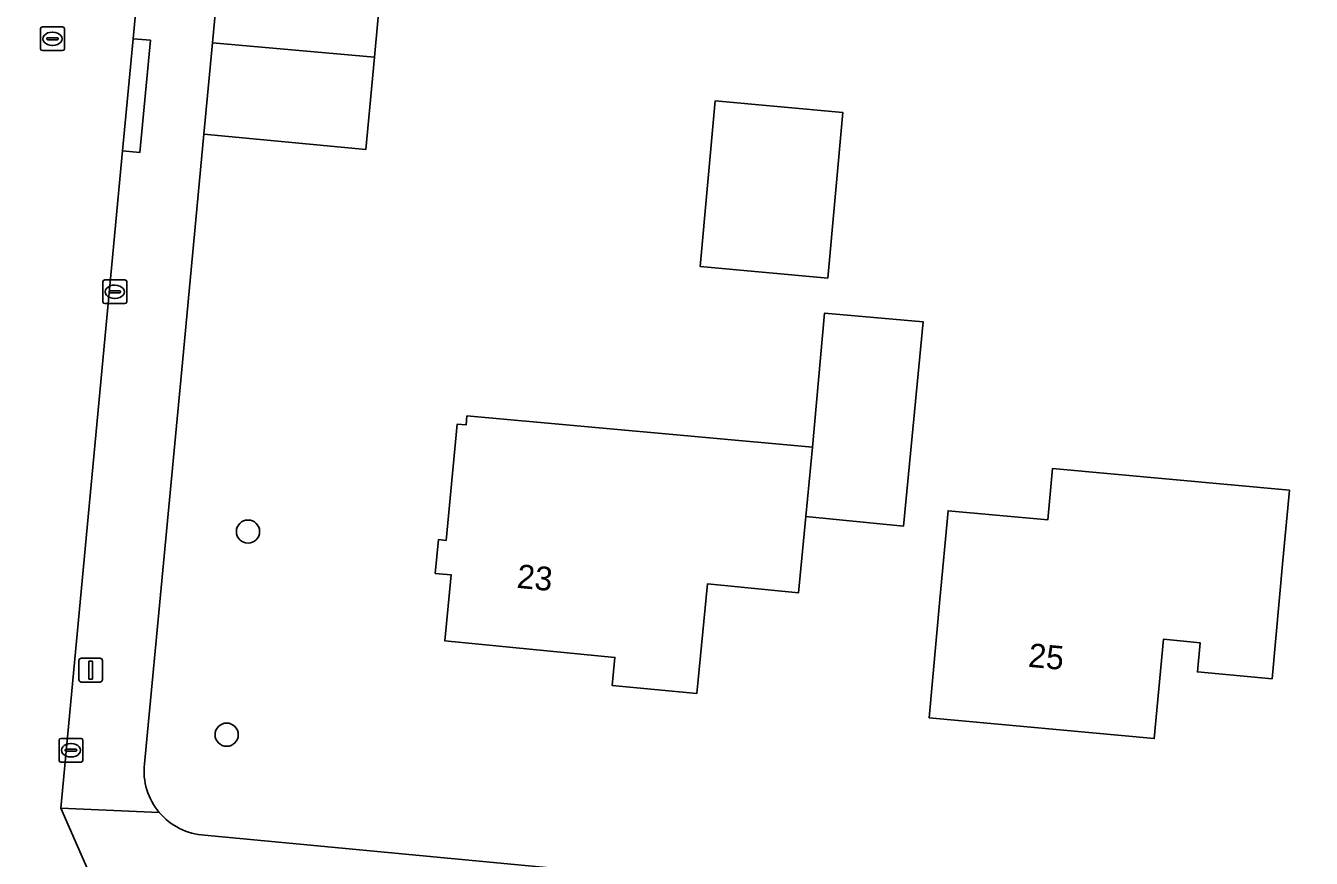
# Model space of a CAD drawing. Extents: x 162184 to 163154, y 385507 to 386516.
# Drawn here: x 162330 to 162384.1, y 385729.1 to 385764.2 of the extents above; entities that cross this region are included whole.
import ezdxf

# ---------------------------------------------------------------- set-up
doc = ezdxf.new("R2010")
doc.units = 0
for name, color, linetype in [('IMGEO_Boom', 7, 'Continuous'), ('IMGEO_Erf', 7, 'Continuous'), ('IMGEO_Groenvoorziening', 7, 'Continuous'), ('IMGEO_Kolk', 7, 'Continuous'), ('IMGEO_Lichtmast', 7, 'Continuous'), ('IMGEO_Pand', 7, 'Continuous'), ('IMGEO_Pand_nummerreeks', 7, 'Continuous'), ('IMGEO_Rijbaan_lokaal_open', 7, 'Continuous'), ('IMGEO_Rioolput', 7, 'Continuous'), ('IMGEO_Voetpad_open', 7, 'Continuous')]:
    doc.layers.add(name, color=color, linetype=linetype)

msp = doc.modelspace()

# ---------------------------------------------------------------- linework, layer by layer
at = {"layer": 'IMGEO_Boom'}
for centre in [(162339.375, 385742.883), (162338.477, 385734.329)]:
    msp.add_circle(centre, 0.489, dxfattribs=at)
at = {"layer": 'IMGEO_Erf'}
for points in [[(162337.549, 385730.101), (162341.556, 385729.721), (162447.49, 385719.675), (162447.817, 385719.644), (162448.146, 385719.642), (162448.474, 385719.67), (162448.798, 385719.727), (162449.115, 385719.812), (162449.424, 385719.926), (162449.721, 385720.066), (162450.004, 385720.233), (162450.272, 385720.424), (162450.521, 385720.638), (162450.75, 385720.874), (162450.957, 385721.13), (162451.141, 385721.402), (162451.299, 385721.69), (162451.431, 385721.992), (162451.536, 385722.303), (162451.611, 385722.618), (162457.633, 385750), (162471.711, 385814.014)], [(162385.288, 385773.348), (162380.924, 385773.758), (162377.186, 385774.109), (162377.034, 385772.49), (162373.767, 385772.796), (162373.284, 385767.651), (162368.912, 385768.061), (162369.148, 385770.582), (162369.031, 385770.593), (162364.25, 385771.042), (162364.644, 385775.246), (162357.691, 385775.899), (162350.64, 385776.561), (162350.248, 385772.378), (162345.611, 385772.814), (162344.694, 385762.863), (162344.337, 385758.978), (162337.522, 385759.63), (162336.612, 385750), (162335.015, 385733.1)]]:
    msp.add_lwpolyline(points, dxfattribs=at)
for points in [[(162363.785, 385753.564), (162358.417, 385754.049), (162359.046, 385761.02), (162364.414, 385760.536)], [(162366.976, 385743.118), (162362.861, 385743.514), (162362.552, 385740.308), (162358.713, 385740.677), (162358.268, 385736.058), (162354.711, 385736.401), (162354.825, 385737.586), (162347.662, 385738.276), (162347.93, 385741.06), (162347.261, 385741.125), (162347.398, 385742.546), (162347.713, 385742.515), (162348.185, 385747.413), (162348.555, 385747.377), (162348.592, 385747.756), (162363.143, 385746.443), (162363.652, 385752.09), (162367.803, 385751.716)], [(162382.486, 385736.688), (162379.343, 385736.977), (162379.455, 385738.205), (162377.91, 385738.348), (162377.526, 385734.169), (162368.045, 385735.041), (162368.503, 385740.021), (162368.847, 385743.765), (162373.047, 385743.379), (162373.246, 385745.545), (162383.216, 385744.628), (162382.944, 385741.668)]]:
    msp.add_lwpolyline(points, close=True, dxfattribs=at)
for centre, radius, start, end in [((162337.702, 385732.799), 2.703, 173.6089, 220.1748), ((162337.701, 385732.8), 2.704, 220.2073, 266.7824)]:
    msp.add_arc(centre, radius, start, end, dxfattribs=at)
at = {"layer": 'IMGEO_Groenvoorziening'}
msp.add_lwpolyline([(162345.611, 385772.814), (162346.682, 385784.225), (162347.106, 385789.192), (162340.338, 385789.823), (162337.881, 385763.475), (162344.694, 385762.863)], close=True, dxfattribs=at)
at = {"layer": 'IMGEO_Kolk'}
for p, q in [((162333.268, 385752.56), (162333.268, 385753.412)), ((162333.343, 385753.486), (162334.195, 385753.486)), ((162334.269, 385753.412), (162334.269, 385752.56)), ((162333.527, 385752.98), (162333.527, 385752.992)), ((162333.965, 385752.943), (162333.567, 385752.943)), ((162333.57, 385753.029), (162333.968, 385753.029)), ((162333.756, 385753.266), (162333.781, 385753.266)), ((162334.011, 385752.992), (162334.011, 385752.98)), ((162334.195, 385752.486), (162333.343, 385752.486)), ((162333.779, 385752.706), (162333.754, 385752.706)), ((162331.421, 385733.247), (162331.421, 385734.099)), ((162331.496, 385734.173), (162332.348, 385734.173)), ((162331.909, 385733.953), (162331.934, 385733.953)), ((162332.422, 385734.099), (162332.422, 385733.247)), ((162331.68, 385733.667), (162331.68, 385733.679)), ((162332.118, 385733.63), (162331.72, 385733.63)), ((162331.723, 385733.716), (162332.121, 385733.716)), ((162331.932, 385733.393), (162331.907, 385733.393)), ((162332.164, 385733.679), (162332.164, 385733.667)), ((162332.348, 385733.173), (162331.496, 385733.173))]:
    msp.add_line(p, q, dxfattribs=at)
for points in [[(162333.268, 385752.56), (162333.268, 385753.412)], [(162333.343, 385753.486), (162334.195, 385753.486)], [(162334.269, 385753.412), (162334.269, 385752.56)], [(162334.195, 385752.486), (162333.343, 385752.486)], [(162331.421, 385733.247), (162331.421, 385734.099)], [(162331.496, 385734.173), (162332.348, 385734.173)], [(162332.422, 385734.099), (162332.422, 385733.247)], [(162332.348, 385733.173), (162331.496, 385733.173)]]:
    msp.add_lwpolyline(points, dxfattribs=at)
for centre, radius, start, end in [((162333.345, 385753.41), 0.0765, 91.552, 178.448), ((162333.345, 385753.41), 0.0765, 91.552, 178.448), ((162334.193, 385753.41), 0.0765, 1.552, 88.448), ((162334.193, 385753.41), 0.0765, 1.552, 88.448), ((162333.567, 385752.989), 0.0403, 85.8775, 175.7526), ((162333.564, 385752.979), 0.0366, 178.938, 274.7102), ((162333.968, 385752.986), 0.043, 264.8664, 352.4533), ((162333.972, 385752.991), 0.0386, 1.7309, 96.639), ((162333.345, 385752.562), 0.0765, 181.552, 268.448), ((162333.345, 385752.562), 0.0765, 181.552, 268.448), ((162334.193, 385752.562), 0.0765, 271.552, 358.448), ((162334.193, 385752.562), 0.0765, 271.552, 358.448), ((162331.498, 385734.097), 0.0765, 91.552, 178.448), ((162331.498, 385734.097), 0.0765, 91.552, 178.448), ((162332.346, 385734.097), 0.0765, 1.552, 88.448), ((162332.346, 385734.097), 0.0765, 1.552, 88.448), ((162331.72, 385733.676), 0.0403, 85.8775, 175.7526), ((162331.717, 385733.666), 0.0366, 178.938, 274.7102), ((162332.121, 385733.673), 0.043, 264.8664, 352.4533), ((162332.125, 385733.678), 0.0386, 1.7309, 96.639), ((162331.498, 385733.249), 0.0765, 181.552, 268.448), ((162331.498, 385733.249), 0.0765, 181.552, 268.448), ((162332.346, 385733.249), 0.0765, 271.552, 358.448), ((162332.346, 385733.249), 0.0765, 271.552, 358.448)]:
    msp.add_arc(centre, radius, start, end, dxfattribs=at)
for centre, major_axis, ratio, start_param, end_param in [((162333.755, 385752.986), (-0.387, 0.002), 0.722429, 4.712389, 7.853982), ((162333.78, 385752.986), (-0.39, 0.002), 0.717154, 1.570796, 4.712389), ((162331.908, 385733.673), (-0.387, 0.002), 0.722429, 4.712389, 7.853982), ((162331.933, 385733.673), (-0.39, 0.002), 0.717154, 1.570796, 4.712389)]:
    msp.add_ellipse(centre, major_axis=major_axis, ratio=ratio, start_param=start_param, end_param=end_param, dxfattribs=at)
at = {"layer": 'IMGEO_Lichtmast'}
for p, q in [((162332.257, 385736.648), (162332.257, 385737.448)), ((162332.257, 385737.448), (162332.257, 385736.648)), ((162332.357, 385737.548), (162333.147, 385737.548)), ((162333.147, 385737.548), (162332.357, 385737.548)), ((162333.247, 385737.448), (162333.247, 385736.648)), ((162333.247, 385736.648), (162333.247, 385737.448)), ((162333.147, 385736.548), (162332.357, 385736.548)), ((162332.357, 385736.548), (162333.147, 385736.548))]:
    msp.add_line(p, q, dxfattribs=at)
msp.add_lwpolyline([(162332.677, 385737.423), (162332.827, 385737.423), (162332.827, 385736.673), (162332.677, 385736.673), (162332.677, 385737.423)], dxfattribs=at)
for centre, start, end in [((162332.357, 385737.448), 90, 180), ((162332.357, 385737.448), 90, 180), ((162333.147, 385737.448), 0, 90), ((162333.147, 385737.448), 360, 90), ((162332.357, 385736.648), 180, 270), ((162332.357, 385736.648), 180, 270), ((162333.147, 385736.648), 270, 0), ((162333.147, 385736.648), 270, 0)]:
    msp.add_arc(centre, 0.1, start, end, dxfattribs=at)
at = {"layer": 'IMGEO_Pand'}
for points in [[(162364.414, 385760.536), (162359.046, 385761.02), (162358.417, 385754.049), (162363.785, 385753.564)], [(162367.803, 385751.716), (162363.652, 385752.09), (162363.143, 385746.443), (162362.861, 385743.514), (162366.976, 385743.118)], [(162362.861, 385743.514), (162363.143, 385746.443), (162348.592, 385747.756), (162348.555, 385747.377), (162348.185, 385747.413), (162347.713, 385742.515), (162347.398, 385742.546), (162347.261, 385741.125), (162347.93, 385741.06), (162347.662, 385738.276), (162354.825, 385737.586), (162354.711, 385736.401), (162358.268, 385736.058), (162358.713, 385740.677), (162362.552, 385740.308)], [(162368.847, 385743.765), (162368.503, 385740.021), (162368.045, 385735.041), (162377.526, 385734.169), (162377.91, 385738.348), (162379.455, 385738.205), (162379.343, 385736.977), (162382.486, 385736.688), (162382.944, 385741.668), (162383.216, 385744.628), (162373.246, 385745.545), (162373.047, 385743.379)]]:
    msp.add_lwpolyline(points, close=True, dxfattribs=at)
at = {"layer": 'IMGEO_Rijbaan_lokaal_open'}
msp.add_lwpolyline([(162330.873, 385796.534), (162329.97, 385787.042), (162329.296, 385779.892), (162327.803, 385764.055), (162327.435, 385760.157), (162327.152, 385757.156), (162326.635, 385751.709), (162326.477, 385750), (162324.906, 385734.232), (162324.656, 385731.996), (162324.274, 385731.336), (162322.366, 385728.035), (162333.341, 385727.013), (162331.493, 385731.237), (162334.097, 385758.918), (162334.542, 385763.644), (162337.193, 385792.099)], dxfattribs=at)
at = {"layer": 'IMGEO_Rioolput'}
for p, q in [((162330.644, 385763.215), (162330.644, 385764.067)), ((162330.719, 385764.141), (162331.571, 385764.141)), ((162330.946, 385763.684), (162331.344, 385763.684)), ((162331.132, 385763.921), (162331.157, 385763.921)), ((162331.645, 385764.067), (162331.645, 385763.215)), ((162331.571, 385763.141), (162330.719, 385763.141)), ((162330.903, 385763.635), (162330.903, 385763.647)), ((162331.341, 385763.598), (162330.943, 385763.598)), ((162331.155, 385763.361), (162331.13, 385763.361)), ((162331.387, 385763.647), (162331.387, 385763.635))]:
    msp.add_line(p, q, dxfattribs=at)
for points in [[(162330.644, 385763.215), (162330.644, 385764.067)], [(162330.719, 385764.141), (162331.571, 385764.141)], [(162331.645, 385764.067), (162331.645, 385763.215)], [(162331.571, 385763.141), (162330.719, 385763.141)]]:
    msp.add_lwpolyline(points, dxfattribs=at)
for centre, radius, start, end in [((162330.721, 385764.065), 0.0765, 91.552, 178.448), ((162330.721, 385764.065), 0.0765, 91.552, 178.448), ((162330.943, 385763.644), 0.0403, 85.8775, 175.7526), ((162331.348, 385763.646), 0.0386, 1.7309, 96.639), ((162331.569, 385764.065), 0.0765, 1.552, 88.448), ((162331.569, 385764.065), 0.0765, 1.552, 88.448), ((162330.721, 385763.217), 0.0765, 181.552, 268.448), ((162330.721, 385763.217), 0.0765, 181.552, 268.448), ((162330.94, 385763.634), 0.0366, 178.938, 274.7102), ((162331.344, 385763.641), 0.043, 264.8664, 352.4533), ((162331.569, 385763.217), 0.0765, 271.552, 358.448), ((162331.569, 385763.217), 0.0765, 271.552, 358.448)]:
    msp.add_arc(centre, radius, start, end, dxfattribs=at)
for centre, major_axis, ratio, start_param, end_param in [((162331.131, 385763.641), (-0.387, 0.002), 0.722429, 4.712389, 7.853982), ((162331.156, 385763.641), (-0.39, 0.002), 0.717154, 1.570796, 4.712389)]:
    msp.add_ellipse(centre, major_axis=major_axis, ratio=ratio, start_param=start_param, end_param=end_param, dxfattribs=at)
at = {"layer": 'IMGEO_Voetpad_open'}
for points in [[(162337.522, 385759.63), (162337.881, 385763.475), (162340.338, 385789.823), (162340.62, 385792.852)], [(162337.193, 385792.099), (162334.542, 385763.644), (162335.266, 385763.576), (162334.821, 385758.85), (162334.097, 385758.918), (162331.493, 385731.237), (162335.636, 385731.055)], [(162335.015, 385733.1), (162336.612, 385750), (162337.522, 385759.63)], [(162335.636, 385731.055), (162331.493, 385731.237), (162333.341, 385727.013)], [(162341.556, 385729.721), (162337.549, 385730.101)], [(162447.49, 385719.675), (162341.556, 385729.721)]]:
    msp.add_lwpolyline(points, dxfattribs=at)
for points in [[(162335.266, 385763.576), (162334.542, 385763.644), (162334.097, 385758.918), (162334.821, 385758.85)], [(162337.522, 385759.63), (162344.337, 385758.978), (162344.694, 385762.863), (162337.881, 385763.475)]]:
    msp.add_lwpolyline(points, close=True, dxfattribs=at)
for centre, radius, start, end in [((162337.702, 385732.799), 2.703, 173.6089, 220.1748), ((162337.701, 385732.8), 2.704, 220.2073, 266.7824)]:
    msp.add_arc(centre, radius, start, end, dxfattribs=at)

# ---------------------------------------------------------------- texts
at = {"layer": 'IMGEO_Pand_nummerreeks'}
for s, rotation, p in [('23', 354.4996, (162350.663, 385740.519)), ('25', 354.7451, (162372.194, 385737.191))]:
    msp.add_text(s, height=1, rotation=rotation, dxfattribs=at).set_placement(p)

doc.saveas('drawing.dxf')
